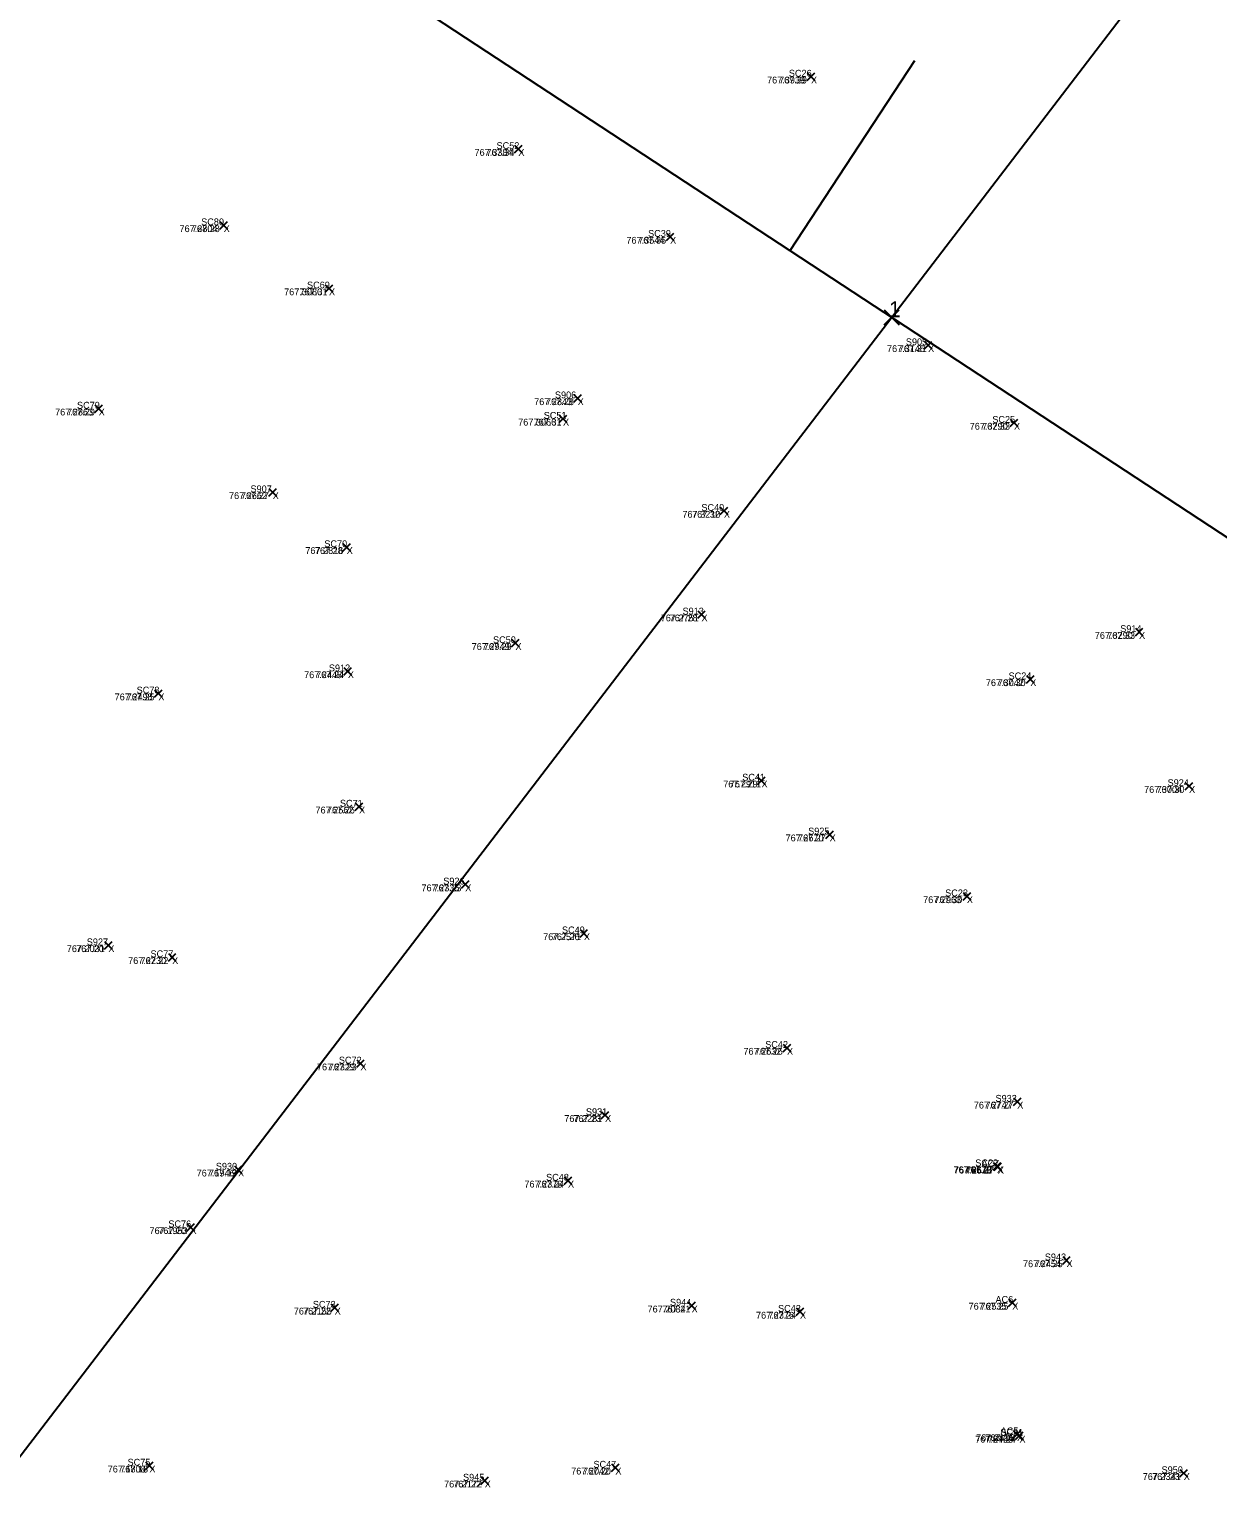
# Model space of a CAD drawing. Extents: x 1845019 to 1877956, y 680444 to 701081.
# Drawn here: x 1857683.62 to 1857694.08, y 694251.31 to 694264.34 of the extents above; entities that cross this region are included whole.
import ezdxf

# ---------------------------------------------------------------- set-up
doc = ezdxf.new("R2010")
doc.units = 0
for name, color, linetype in [('GK_Visualization', 7, 'Continuous'), ('SV_X_CL_Survey_20', 7, 'Continuous'), ('SV_X_Random_Point', 7, 'Continuous'), ('SV_X_Text_Comment', 7, 'Continuous'), ('SV_X_Text_Elevation', 7, 'Continuous'), ('SV_X_Text_Name', 7, 'Continuous')]:
    doc.layers.add(name, color=color, linetype=linetype)

msp = doc.modelspace()

# ---------------------------------------------------------------- linework, layer by layer
at = {"layer": 'GK_Visualization'}
for p, q in [((1857691.143, 694261.746), (1857691.276, 694261.879)), ((1857691.143, 694261.879), (1857691.276, 694261.746))]:
    msp.add_line(p, q, dxfattribs=at)
at = {"layer": 'SV_X_CL_Survey_20'}
for p, q in [((1856038.267, 695346.314), (1858797.327, 693536.085)), ((1849938.531, 684134.245), (1857781.861, 694380.233)), ((1857690.316, 694262.399), (1857691.414, 694264.071))]:
    msp.add_line(p, q, dxfattribs=at)
at = {"layer": 'SV_X_Random_Point'}
for p, q in [((1857690.467, 694263.896), (1857690.534, 694263.963)), ((1857690.467, 694263.963), (1857690.534, 694263.896)), ((1857690.467, 694263.896), (1857690.534, 694263.963)), ((1857690.467, 694263.963), (1857690.534, 694263.896)), ((1857687.89, 694263.259), (1857687.957, 694263.326)), ((1857687.89, 694263.326), (1857687.957, 694263.259)), ((1857687.89, 694263.259), (1857687.957, 694263.326)), ((1857687.89, 694263.326), (1857687.957, 694263.259)), ((1857685.296, 694262.588), (1857685.363, 694262.655)), ((1857685.296, 694262.655), (1857685.363, 694262.588)), ((1857685.296, 694262.588), (1857685.363, 694262.655)), ((1857685.296, 694262.655), (1857685.363, 694262.588)), ((1857689.227, 694262.487), (1857689.293, 694262.553)), ((1857689.227, 694262.553), (1857689.293, 694262.487)), ((1857689.227, 694262.487), (1857689.293, 694262.553)), ((1857689.227, 694262.553), (1857689.293, 694262.487)), ((1857686.224, 694262.033), (1857686.291, 694262.099)), ((1857686.224, 694262.099), (1857686.291, 694262.033)), ((1857686.224, 694262.033), (1857686.291, 694262.099)), ((1857686.224, 694262.099), (1857686.291, 694262.033)), ((1857691.498, 694261.533), (1857691.565, 694261.599)), ((1857691.498, 694261.599), (1857691.565, 694261.533)), ((1857691.498, 694261.533), (1857691.565, 694261.599)), ((1857691.498, 694261.599), (1857691.565, 694261.533)), ((1857688.413, 694261.065), (1857688.48, 694261.132)), ((1857688.413, 694261.132), (1857688.48, 694261.065)), ((1857688.413, 694261.065), (1857688.48, 694261.132)), ((1857688.413, 694261.132), (1857688.48, 694261.065)), ((1857684.197, 694260.974), (1857684.264, 694261.041)), ((1857684.197, 694261.041), (1857684.264, 694260.974)), ((1857684.197, 694260.974), (1857684.264, 694261.041)), ((1857684.197, 694261.041), (1857684.264, 694260.974)), ((1857688.284, 694260.885), (1857688.351, 694260.952)), ((1857688.284, 694260.952), (1857688.351, 694260.885)), ((1857688.284, 694260.885), (1857688.351, 694260.952)), ((1857688.284, 694260.952), (1857688.351, 694260.885)), ((1857692.254, 694260.85), (1857692.321, 694260.916)), ((1857692.254, 694260.916), (1857692.321, 694260.85)), ((1857692.254, 694260.85), (1857692.321, 694260.916)), ((1857692.254, 694260.916), (1857692.321, 694260.85)), ((1857685.728, 694260.239), (1857685.795, 694260.306)), ((1857685.728, 694260.306), (1857685.795, 694260.239)), ((1857685.728, 694260.239), (1857685.795, 694260.306)), ((1857685.728, 694260.306), (1857685.795, 694260.239)), ((1857689.7, 694260.075), (1857689.767, 694260.142)), ((1857689.7, 694260.142), (1857689.767, 694260.075)), ((1857689.7, 694260.075), (1857689.767, 694260.142)), ((1857689.7, 694260.142), (1857689.767, 694260.075)), ((1857686.379, 694259.755), (1857686.446, 694259.822)), ((1857686.379, 694259.822), (1857686.446, 694259.755)), ((1857686.379, 694259.755), (1857686.446, 694259.822)), ((1857686.379, 694259.822), (1857686.446, 694259.755)), ((1857689.503, 694259.163), (1857689.569, 694259.229)), ((1857689.503, 694259.229), (1857689.569, 694259.163)), ((1857689.503, 694259.163), (1857689.569, 694259.229)), ((1857689.503, 694259.229), (1857689.569, 694259.163)), ((1857693.355, 694259.009), (1857693.422, 694259.076)), ((1857693.355, 694259.076), (1857693.422, 694259.009)), ((1857693.355, 694259.009), (1857693.422, 694259.076)), ((1857693.355, 694259.076), (1857693.422, 694259.009)), ((1857687.865, 694258.911), (1857687.932, 694258.978)), ((1857687.865, 694258.978), (1857687.932, 694258.911)), ((1857687.865, 694258.911), (1857687.932, 694258.978)), ((1857687.865, 694258.978), (1857687.932, 694258.911)), ((1857686.389, 694258.662), (1857686.456, 694258.729)), ((1857686.389, 694258.729), (1857686.456, 694258.662)), ((1857686.389, 694258.662), (1857686.456, 694258.729)), ((1857686.389, 694258.729), (1857686.456, 694258.662)), ((1857692.397, 694258.592), (1857692.463, 694258.659)), ((1857692.397, 694258.659), (1857692.463, 694258.592)), ((1857692.397, 694258.592), (1857692.463, 694258.659)), ((1857692.397, 694258.659), (1857692.463, 694258.592)), ((1857684.722, 694258.468), (1857684.789, 694258.534)), ((1857684.722, 694258.534), (1857684.789, 694258.468)), ((1857684.722, 694258.468), (1857684.789, 694258.534)), ((1857684.722, 694258.534), (1857684.789, 694258.468)), ((1857690.03, 694257.701), (1857690.097, 694257.767)), ((1857690.03, 694257.767), (1857690.097, 694257.701)), ((1857690.03, 694257.701), (1857690.097, 694257.767)), ((1857690.03, 694257.767), (1857690.097, 694257.701)), ((1857693.794, 694257.652), (1857693.861, 694257.719)), ((1857693.794, 694257.719), (1857693.861, 694257.652)), ((1857693.794, 694257.652), (1857693.861, 694257.719)), ((1857693.794, 694257.719), (1857693.861, 694257.652)), ((1857686.488, 694257.471), (1857686.555, 694257.538)), ((1857686.488, 694257.538), (1857686.555, 694257.471)), ((1857686.488, 694257.471), (1857686.555, 694257.538)), ((1857686.488, 694257.538), (1857686.555, 694257.471)), ((1857690.631, 694257.226), (1857690.698, 694257.293)), ((1857690.631, 694257.293), (1857690.698, 694257.226)), ((1857690.631, 694257.226), (1857690.698, 694257.293)), ((1857690.631, 694257.293), (1857690.698, 694257.226)), ((1857687.423, 694256.787), (1857687.49, 694256.854)), ((1857687.423, 694256.854), (1857687.49, 694256.787)), ((1857687.423, 694256.787), (1857687.49, 694256.854)), ((1857687.423, 694256.854), (1857687.49, 694256.787)), ((1857691.839, 694256.682), (1857691.906, 694256.749)), ((1857691.839, 694256.749), (1857691.906, 694256.682)), ((1857691.839, 694256.682), (1857691.906, 694256.749)), ((1857691.839, 694256.749), (1857691.906, 694256.682)), ((1857684.282, 694256.251), (1857684.348, 694256.318)), ((1857684.282, 694256.318), (1857684.348, 694256.251)), ((1857684.282, 694256.251), (1857684.348, 694256.318)), ((1857684.282, 694256.318), (1857684.348, 694256.251)), ((1857688.468, 694256.357), (1857688.534, 694256.424)), ((1857688.468, 694256.424), (1857688.534, 694256.357)), ((1857688.468, 694256.357), (1857688.534, 694256.424)), ((1857688.468, 694256.424), (1857688.534, 694256.357)), ((1857684.844, 694256.146), (1857684.91, 694256.213)), ((1857684.844, 694256.213), (1857684.91, 694256.146)), ((1857684.844, 694256.146), (1857684.91, 694256.213)), ((1857684.844, 694256.213), (1857684.91, 694256.146)), ((1857690.256, 694255.348), (1857690.323, 694255.415)), ((1857690.256, 694255.415), (1857690.323, 694255.348)), ((1857690.256, 694255.348), (1857690.323, 694255.415)), ((1857690.256, 694255.415), (1857690.323, 694255.348)), ((1857686.501, 694255.211), (1857686.568, 694255.278)), ((1857686.501, 694255.278), (1857686.568, 694255.211)), ((1857686.501, 694255.211), (1857686.568, 694255.278)), ((1857686.501, 694255.278), (1857686.568, 694255.211)), ((1857692.282, 694254.875), (1857692.349, 694254.941)), ((1857692.282, 694254.941), (1857692.349, 694254.875)), ((1857692.282, 694254.875), (1857692.349, 694254.941)), ((1857692.282, 694254.941), (1857692.349, 694254.875)), ((1857688.654, 694254.757), (1857688.72, 694254.823)), ((1857688.654, 694254.823), (1857688.72, 694254.757)), ((1857688.654, 694254.757), (1857688.72, 694254.823)), ((1857688.654, 694254.823), (1857688.72, 694254.757)), ((1857692.104, 694254.307), (1857692.17, 694254.373)), ((1857692.104, 694254.373), (1857692.17, 694254.307)), ((1857692.104, 694254.307), (1857692.17, 694254.373)), ((1857692.104, 694254.373), (1857692.17, 694254.307)), ((1857692.112, 694254.302), (1857692.178, 694254.369)), ((1857692.112, 694254.369), (1857692.178, 694254.302)), ((1857692.112, 694254.302), (1857692.178, 694254.369)), ((1857692.112, 694254.369), (1857692.178, 694254.302)), ((1857685.424, 694254.276), (1857685.491, 694254.343)), ((1857685.424, 694254.343), (1857685.491, 694254.276)), ((1857685.424, 694254.276), (1857685.491, 694254.343)), ((1857685.424, 694254.343), (1857685.491, 694254.276)), ((1857688.328, 694254.179), (1857688.394, 694254.246)), ((1857688.328, 694254.246), (1857688.394, 694254.179)), ((1857688.328, 694254.179), (1857688.394, 694254.246)), ((1857688.328, 694254.246), (1857688.394, 694254.179)), ((1857685.005, 694253.77), (1857685.072, 694253.836)), ((1857685.005, 694253.836), (1857685.072, 694253.77)), ((1857685.005, 694253.77), (1857685.072, 694253.836)), ((1857685.005, 694253.836), (1857685.072, 694253.77)), ((1857692.716, 694253.478), (1857692.782, 694253.545)), ((1857692.716, 694253.545), (1857692.782, 694253.478)), ((1857692.716, 694253.478), (1857692.782, 694253.545)), ((1857692.716, 694253.545), (1857692.782, 694253.478)), ((1857686.273, 694253.061), (1857686.34, 694253.128)), ((1857686.273, 694253.128), (1857686.34, 694253.061)), ((1857686.273, 694253.061), (1857686.34, 694253.128)), ((1857686.273, 694253.128), (1857686.34, 694253.061)), ((1857689.416, 694253.08), (1857689.483, 694253.146)), ((1857689.416, 694253.146), (1857689.483, 694253.08)), ((1857689.416, 694253.08), (1857689.483, 694253.146)), ((1857689.416, 694253.146), (1857689.483, 694253.08)), ((1857690.369, 694253.026), (1857690.436, 694253.093)), ((1857690.369, 694253.093), (1857690.436, 694253.026)), ((1857690.369, 694253.026), (1857690.436, 694253.093)), ((1857690.369, 694253.093), (1857690.436, 694253.026)), ((1857692.238, 694253.105), (1857692.305, 694253.172)), ((1857692.238, 694253.172), (1857692.305, 694253.105)), ((1857692.238, 694253.105), (1857692.305, 694253.172)), ((1857692.238, 694253.172), (1857692.305, 694253.105)), ((1857692.279, 694251.947), (1857692.346, 694252.014)), ((1857692.279, 694252.014), (1857692.346, 694251.947)), ((1857692.279, 694251.947), (1857692.346, 694252.014)), ((1857692.279, 694252.014), (1857692.346, 694251.947)), ((1857692.301, 694251.935), (1857692.368, 694252.002)), ((1857692.301, 694252.002), (1857692.368, 694251.935)), ((1857692.301, 694251.935), (1857692.368, 694252.002)), ((1857692.301, 694252.002), (1857692.368, 694251.935)), ((1857684.642, 694251.672), (1857684.709, 694251.738)), ((1857684.642, 694251.738), (1857684.709, 694251.672)), ((1857684.642, 694251.672), (1857684.709, 694251.738)), ((1857684.642, 694251.738), (1857684.709, 694251.672)), ((1857688.744, 694251.654), (1857688.811, 694251.721)), ((1857688.744, 694251.721), (1857688.811, 694251.654)), ((1857688.744, 694251.654), (1857688.811, 694251.721)), ((1857688.744, 694251.721), (1857688.811, 694251.654)), ((1857693.748, 694251.606), (1857693.815, 694251.672)), ((1857693.748, 694251.672), (1857693.815, 694251.606)), ((1857693.748, 694251.606), (1857693.815, 694251.672)), ((1857693.748, 694251.672), (1857693.815, 694251.606)), ((1857687.595, 694251.54), (1857687.662, 694251.607)), ((1857687.595, 694251.607), (1857687.662, 694251.54)), ((1857687.595, 694251.54), (1857687.662, 694251.607)), ((1857687.595, 694251.607), (1857687.662, 694251.54))]:
    msp.add_line(p, q, dxfattribs=at)

# ---------------------------------------------------------------- texts
at = {"layer": 'GK_Visualization'}
msp.add_text('1', height=0.14, dxfattribs=at).set_placement((1857691.186, 694261.813))
at = {"layer": 'SV_X_Text_Comment'}
for p in [(1857690.5, 694263.87), (1857687.924, 694263.233), (1857685.33, 694262.562), (1857689.26, 694262.46), (1857686.257, 694262.006), (1857691.531, 694261.506), (1857684.23, 694260.948), (1857688.446, 694261.039), (1857688.317, 694260.859), (1857692.287, 694260.823), (1857685.762, 694260.212), (1857689.733, 694260.048), (1857686.413, 694259.729), (1857689.536, 694259.136), (1857693.388, 694258.982), (1857687.898, 694258.884), (1857686.423, 694258.636), (1857692.43, 694258.566), (1857684.755, 694258.441), (1857690.064, 694257.674), (1857693.828, 694257.626), (1857686.522, 694257.445), (1857690.664, 694257.2), (1857687.456, 694256.76), (1857691.872, 694256.656), (1857688.501, 694256.33), (1857684.315, 694256.225), (1857684.877, 694256.12), (1857690.289, 694255.322), (1857686.534, 694255.184), (1857692.315, 694254.848), (1857688.687, 694254.73), (1857685.457, 694254.25), (1857692.137, 694254.28), (1857692.145, 694254.276), (1857688.361, 694254.153), (1857685.038, 694253.743), (1857692.749, 694253.452), (1857686.307, 694253.035), (1857689.449, 694253.053), (1857690.403, 694252.999), (1857692.271, 694253.078), (1857692.313, 694251.921), (1857692.335, 694251.908), (1857684.676, 694251.645), (1857688.778, 694251.627), (1857693.781, 694251.579), (1857687.628, 694251.513)]:
    msp.add_text('X', height=0.06, dxfattribs=at).set_placement(p)
at = {"layer": 'SV_X_Text_Elevation'}
for s, p in [('767.3939', (1857690.113, 694263.87)), ('767.39', (1857690.219, 694263.87)), ('767.3384', (1857687.538, 694263.233)), ('767.34', (1857687.643, 694263.233)), ('767.2804', (1857684.941, 694262.562)), ('767.28', (1857685.05, 694262.562)), ('767.3544', (1857688.875, 694262.46)), ('767.35', (1857688.979, 694262.46)), ('767.3080', (1857685.862, 694262.006)), ('767.31', (1857685.999, 694262.006)), ('767.3145', (1857691.169, 694261.506)), ('767.31', (1857691.273, 694261.506)), ('767.2863', (1857683.846, 694260.948)), ('767.29', (1857683.951, 694260.948)), ('767.2843', (1857688.063, 694261.039)), ('767.28', (1857688.167, 694261.039)), ('767.3066', (1857687.922, 694260.859)), ('767.31', (1857688.059, 694260.859)), ('767.3290', (1857691.897, 694260.823)), ('767.33', (1857692.006, 694260.823)), ('767.2662', (1857685.377, 694260.212)), ('767.27', (1857685.482, 694260.212)), ('767.3210', (1857689.368, 694260.048)), ('767.32', (1857689.453, 694260.048)), ('767.2816', (1857686.049, 694259.729)), ('767.28', (1857686.133, 694259.729)), ('767.2751', (1857689.177, 694259.136)), ('767.28', (1857689.256, 694259.136)), ('767.3290', (1857692.998, 694258.982)), ('767.33', (1857693.107, 694258.982)), ('767.2949', (1857687.513, 694258.884)), ('767.29', (1857687.619, 694258.884)), ('767.2448', (1857686.038, 694258.636)), ('767.24', (1857686.144, 694258.636)), ('767.3042', (1857692.039, 694258.566)), ('767.30', (1857692.144, 694258.566)), ('767.2498', (1857684.37, 694258.441)), ('767.25', (1857684.476, 694258.441)), ('767.2911', (1857689.727, 694257.674)), ('767.29', (1857689.784, 694257.674)), ('767.3004', (1857693.432, 694257.626)), ('767.30', (1857693.542, 694257.626)), ('767.2562', (1857686.138, 694257.445)), ('767.26', (1857686.239, 694257.445)), ('767.2670', (1857690.276, 694257.2)), ('767.27', (1857690.385, 694257.2)), ('767.2335', (1857687.071, 694256.76)), ('767.23', (1857687.177, 694256.76)), ('767.2963', (1857691.487, 694256.656)), ('767.30', (1857691.586, 694256.656)), ('767.2571', (1857688.142, 694256.33)), ('767.26', (1857688.218, 694256.33)), ('767.2031', (1857683.949, 694256.225)), ('767.20', (1857684.031, 694256.225)), ('767.2230', (1857684.489, 694256.12)), ('767.22', (1857684.598, 694256.12)), ('767.2632', (1857689.905, 694255.322)), ('767.26', (1857690.006, 694255.322)), ('767.2329', (1857686.151, 694255.184)), ('767.23', (1857686.255, 694255.184)), ('767.2747', (1857691.933, 694254.848)), ('767.27', (1857692.036, 694254.848)), ('767.2281', (1857688.328, 694254.73)), ('767.23', (1857688.408, 694254.73)), ('767.1946', (1857685.092, 694254.25)), ('767.19', (1857685.2, 694254.25)), ('767.2679', (1857691.754, 694254.28)), ('767.2676', (1857691.758, 694254.276)), ('767.27', (1857691.858, 694254.28)), ('767.27', (1857691.866, 694254.276)), ('767.2378', (1857687.977, 694254.153)), ('767.24', (1857688.082, 694254.153)), ('767.1953', (1857684.677, 694253.743)), ('767.20', (1857684.754, 694253.743)), ('767.2454', (1857692.366, 694253.452)), ('767.25', (1857692.47, 694253.452)), ('767.2155', (1857685.947, 694253.035)), ('767.22', (1857686.028, 694253.035)), ('767.2084', (1857689.061, 694253.053)), ('767.21', (1857689.193, 694253.053)), ('767.2376', (1857690.016, 694252.999)), ('767.24', (1857690.124, 694252.999)), ('767.2535', (1857691.887, 694253.078)), ('767.25', (1857691.992, 694253.078)), ('767.2408', (1857691.945, 694251.908)), ('767.2415', (1857691.953, 694251.921)), ('767.24', (1857692.034, 694251.921)), ('767.24', (1857692.056, 694251.908)), ('767.1808', (1857684.309, 694251.645)), ('767.18', (1857684.419, 694251.645)), ('767.2042', (1857688.389, 694251.627)), ('767.20', (1857688.493, 694251.627)), ('767.2341', (1857693.42, 694251.579)), ('767.23', (1857693.502, 694251.579)), ('767.2172', (1857687.27, 694251.513)), ('767.22', (1857687.35, 694251.513))]:
    msp.add_text(s, height=0.06, dxfattribs=at).set_placement(p)
at = {"layer": 'SV_X_Text_Name'}
for s, p in [('SC26', (1857690.305, 694263.93)), ('SC26', (1857690.305, 694263.93)), ('SC52', (1857687.732, 694263.293)), ('SC52', (1857687.732, 694263.293)), ('SC80', (1857685.132, 694262.622)), ('SC80', (1857685.132, 694262.622)), ('SC39', (1857689.066, 694262.52)), ('SC39', (1857689.066, 694262.52)), ('SC69', (1857686.064, 694262.066)), ('SC69', (1857686.064, 694262.066)), ('S905', (1857691.335, 694261.566)), ('S905', (1857691.335, 694261.566)), ('S906', (1857688.246, 694261.099)), ('S906', (1857688.246, 694261.099)), ('SC79', (1857684.039, 694261.008)), ('SC79', (1857684.039, 694261.008)), ('SC51', (1857688.147, 694260.919)), ('SC51', (1857688.148, 694260.919)), ('SC25', (1857692.096, 694260.883)), ('SC25', (1857692.096, 694260.883)), ('S907', (1857685.566, 694260.272)), ('S907', (1857685.566, 694260.272)), ('SC40', (1857689.535, 694260.108)), ('SC40', (1857689.535, 694260.108)), ('SC70', (1857686.216, 694259.789)), ('SC70', (1857686.216, 694259.789)), ('S913', (1857689.369, 694259.196)), ('S913', (1857689.369, 694259.196)), ('S914', (1857693.222, 694259.042)), ('S914', (1857693.222, 694259.042)), ('SC50', (1857687.701, 694258.944)), ('SC50', (1857687.701, 694258.944)), ('S912', (1857686.256, 694258.696)), ('S912', (1857686.256, 694258.696)), ('SC24', (1857692.239, 694258.626)), ('SC24', (1857692.239, 694258.626)), ('SC78', (1857684.564, 694258.501)), ('SC78', (1857684.564, 694258.501)), ('SC41', (1857689.894, 694257.734)), ('SC41', (1857689.895, 694257.734)), ('S924', (1857693.639, 694257.686)), ('S924', (1857693.639, 694257.686)), ('SC71', (1857686.353, 694257.505)), ('SC71', (1857686.354, 694257.505)), ('S925', (1857690.475, 694257.26)), ('S925', (1857690.475, 694257.26)), ('S926', (1857687.263, 694256.82)), ('S926', (1857687.263, 694256.82)), ('SC23', (1857691.681, 694256.716)), ('SC23', (1857691.681, 694256.716)), ('SC49', (1857688.308, 694256.39)), ('SC49', (1857688.308, 694256.39)), ('S927', (1857684.125, 694256.285)), ('S927', (1857684.125, 694256.285)), ('SC77', (1857684.686, 694256.18)), ('SC77', (1857684.686, 694256.18)), ('SC42', (1857690.097, 694255.382)), ('SC42', (1857690.097, 694255.382)), ('SC72', (1857686.344, 694255.244)), ('SC72', (1857686.344, 694255.244)), ('S932', (1857692.124, 694254.908)), ('S932', (1857692.124, 694254.908)), ('S931', (1857688.518, 694254.79)), ('S931', (1857688.519, 694254.79)), ('S930', (1857685.261, 694254.31)), ('S930', (1857685.261, 694254.31)), ('SC22', (1857691.946, 694254.34)), ('SC22', (1857691.946, 694254.34)), ('AC7', (1857692.001, 694254.336)), ('AC7', (1857692.001, 694254.336)), ('SC48', (1857688.168, 694254.213)), ('SC48', (1857688.168, 694254.213)), ('SC76', (1857684.843, 694253.803)), ('SC76', (1857684.843, 694253.803)), ('S943', (1857692.558, 694253.512)), ('S943', (1857692.558, 694253.512)), ('AC6', (1857692.124, 694253.138)), ('AC6', (1857692.124, 694253.138)), ('SC73', (1857686.115, 694253.095)), ('SC73', (1857686.115, 694253.095)), ('S944', (1857689.259, 694253.113)), ('S944', (1857689.259, 694253.113)), ('SC43', (1857690.21, 694253.059)), ('SC43', (1857690.21, 694253.059)), ('AC5', (1857692.169, 694251.981)), ('AC5', (1857692.169, 694251.981)), ('SC21', (1857692.167, 694251.968)), ('SC21', (1857692.166, 694251.968)), ('SC75', (1857684.484, 694251.705)), ('SC75', (1857684.484, 694251.705)), ('SC47', (1857688.585, 694251.687)), ('SC47', (1857688.585, 694251.687)), ('S945', (1857687.437, 694251.573)), ('S945', (1857687.437, 694251.573)), ('S950', (1857693.586, 694251.639)), ('S950', (1857693.586, 694251.639))]:
    msp.add_text(s, height=0.06, dxfattribs=at).set_placement(p)

doc.saveas('drawing.dxf')
